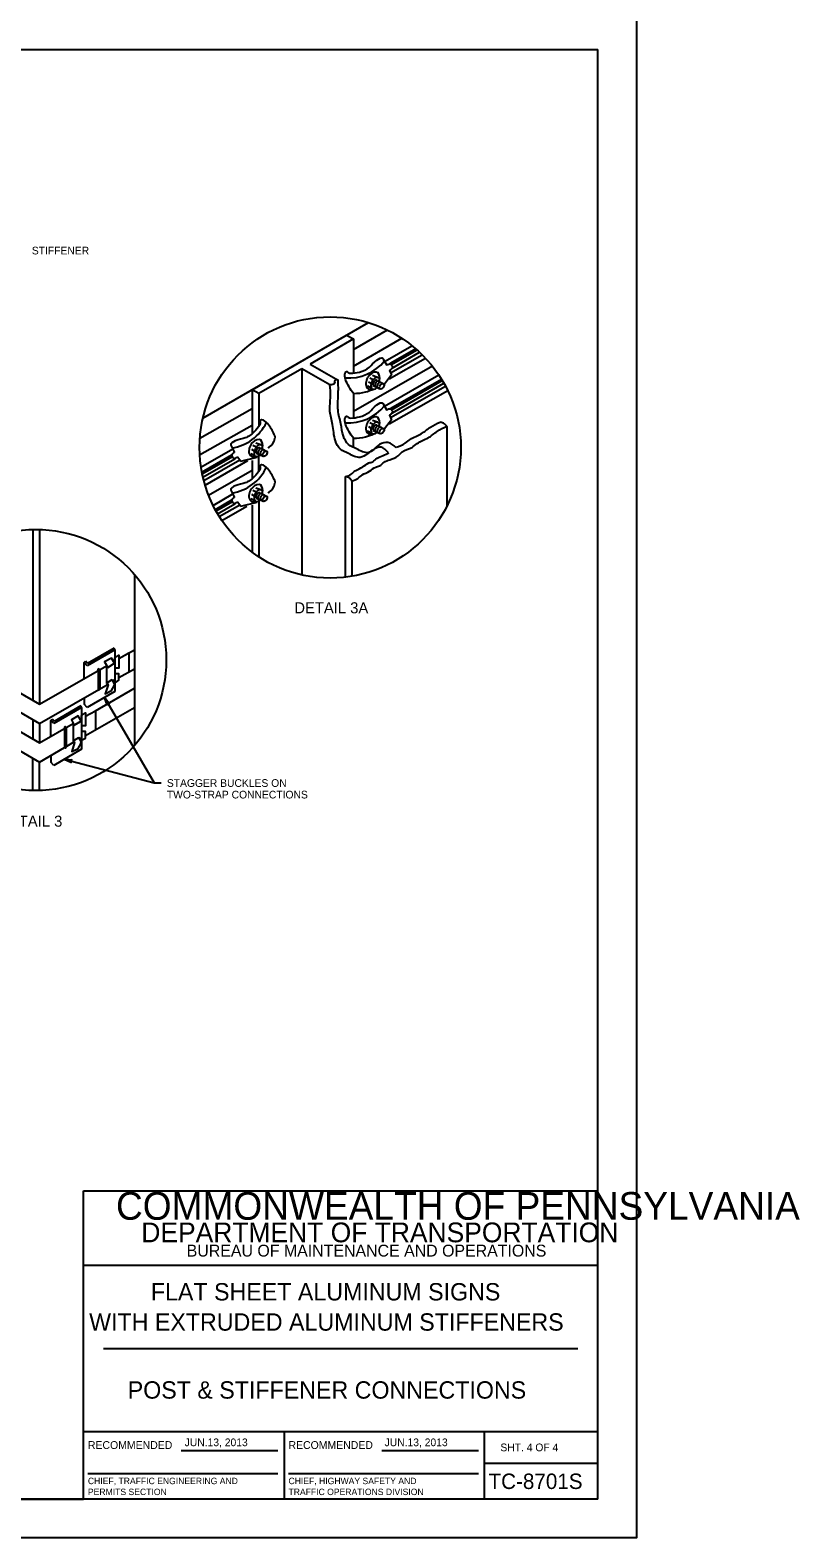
# Model space of a CAD drawing. Extents: x 650495 to 652241, y 298458 to 299646.
# Drawn here: x 651942 to 652241, y 298458 to 299044 of the extents above; entities that cross this region are included whole.
import ezdxf

# ---------------------------------------------------------------- set-up
doc = ezdxf.new("R2010")
doc.units = 0
for name, color, linetype in [('1', 7, 'Continuous'), ('2', 7, 'Continuous'), ('3', 7, 'Continuous'), ('PLT-BNDY', 7, 'Continuous')]:
    doc.layers.add(name, color=color, linetype=linetype)

# ---------------------------------------------------------------- blocks, each defined once
blk = doc.blocks.new('RARROW')
at = {"layer": '3'}
blk.add_lwpolyline([(-2.2695, 0.285), (-2.184875, 0.12075), (0, 0), (-2.2695, 0.285), (-2.38575, 0.384625), (0, 0), (-2.183125, -0.108), (-2.262875, -0.2705), (0, 0), (-2.38575, -0.379125), (-2.262875, -0.2705)], dxfattribs=at)

msp = doc.modelspace()

# ---------------------------------------------------------------- linework, layer by layer
at = {"layer": '1'}
for p, q in [((651376.31, 299036.63), (652162.31, 299036.63)), ((652162.31, 298472.63), (652162.31, 299036.63)), ((651962.31, 298472.63), (651962.31, 298592.63)), ((651962.31, 298592.63), (652162.31, 298592.63)), ((652162.31, 298563.63), (651962.31, 298563.63)), ((651970.06, 298531.31), (652154.56, 298531.31)), ((651962.31, 298499), (652162.31, 298499)), ((652040.31, 298499), (652040.31, 298472.63)), ((652118.19, 298472.63), (652118.19, 298499)), ((652000.24, 298491.57), (652037.87, 298491.57)), ((652078.24, 298491.57), (652115.87, 298491.57)), ((651963.99, 298482.68), (652037.87, 298482.68)), ((652041.99, 298482.68), (652115.87, 298482.68)), ((652118.19, 298486.63), (652162.31, 298486.63)), ((652162.31, 298472.63), (651376.31, 298472.63)), ((651376.31, 298472.63), (651962.31, 298472.63))]:
    msp.add_line(p, q, dxfattribs=at)
at = {"layer": '2'}
for p, q in [((652008.69, 298893.25), (652073.06, 298930.38)), ((652067.31, 298919.88), (652080.44, 298927.5)), ((652080.44, 298927.5), (652080.44, 298927.5)), ((652027.81, 298904.25), (652064.56, 298925.5)), ((652067.31, 298924), (652050.44, 298914.25)), ((652064.56, 298925.5), (652067.31, 298924)), ((652067.31, 298913.38), (652086.06, 298924.25)), ((652067.31, 298924), (652067.31, 298910.79)), ((652078.81, 298916.13), (652080.19, 298913.75)), ((652079.56, 298915.4), (652089.94, 298921.38)), ((652081.19, 298908.45), (652095.31, 298916.5)), ((652091.56, 298920.13), (652081.59, 298914.4)), ((652081.69, 298910.88), (652093.94, 298917.88)), ((652082.04, 298914.01), (652092.06, 298919.75)), ((652082.31, 298912.63), (652092.94, 298918.88)), ((652047.19, 298912.38), (652030.44, 298902.75)), ((652047.19, 298912.38), (652047.19, 298832.13)), ((652058.05, 298906.12), (652047.19, 298912.38)), ((652050.44, 298914.25), (652061.25, 298908.02)), ((652067.31, 298895.95), (652097.94, 298913.5)), ((652074.69, 298909.88), (652076.56, 298909.13)), ((652082.06, 298910), (652079.31, 298906.44)), ((652079.34, 298897.84), (652100.44, 298910)), ((652081.31, 298911.75), (652082.06, 298910)), ((652027.81, 298904.25), (652027.81, 298887.25)), ((652030.44, 298902.75), (652027.81, 298904.25)), ((652072.69, 298905.75), (652074.44, 298904.75)), ((652073.06, 298907.38), (652074.19, 298906.75)), ((652073.69, 298908.88), (652074.94, 298908.25)), ((652074.19, 298907.75), (652074.19, 298907.75)), ((652074.94, 298905.88), (652077.56, 298904.63)), ((652076.44, 298907.88), (652078.81, 298906.63)), ((652081.19, 298891.02), (652103.92, 298903.98)), ((652081.54, 298896.9), (652101.44, 298908.38)), ((652081.69, 298893.45), (652103.07, 298905.67)), ((652082, 298896.43), (652101.81, 298907.88)), ((652082.44, 298895.22), (652102.44, 298906.75)), ((652030.44, 298902.75), (652030.44, 298890.13)), ((652067.31, 298902.65), (652067.31, 298893.24)), ((652078.81, 298898.7), (652080.19, 298896.32)), ((652007.56, 298885.38), (652027.81, 298897)), ((652074.69, 298892.45), (652076.56, 298891.7)), ((652082.06, 298892.57), (652079.31, 298889.01)), ((652081.31, 298894.32), (652082.06, 298892.57)), ((652007.44, 298878.88), (652027.81, 298890.5)), ((652072.69, 298888.32), (652074.44, 298887.32)), ((652073.06, 298889.95), (652074.19, 298889.32)), ((652073.69, 298891.45), (652074.94, 298890.82)), ((652074.19, 298890.32), (652074.19, 298890.32)), ((652074.94, 298888.45), (652077.56, 298887.2)), ((652076.44, 298890.45), (652078.81, 298889.2)), ((652103.56, 298889.99), (652103.56, 298858.75)), ((652007.94, 298874.13), (652020.31, 298881.25)), ((652019.69, 298882.38), (652021.06, 298879.88)), ((652027.56, 298881.13), (652028.69, 298880.5)), ((652028.19, 298882.63), (652029.56, 298882)), ((652028.69, 298881.5), (652028.69, 298881.5)), ((652029.31, 298883.63), (652031.19, 298882.88)), ((652030.94, 298881.63), (652033.44, 298880.38)), ((652067.31, 298881.77), (652067.31, 298885.22)), ((652008.31, 298872.13), (652019.94, 298878.88)), ((652008.44, 298871.5), (652020.44, 298878.38)), ((652008.69, 298870.25), (652021.19, 298877.38)), ((652009.06, 298868.88), (652023.06, 298877)), ((652009.56, 298867.13), (652026.22, 298876.68)), ((652022.31, 298878), (652023.44, 298876.5)), ((652023.44, 298876.5), (652029.76, 298878.05)), ((652027.31, 298879.5), (652028.94, 298878.5)), ((652027.81, 298876.77), (652027.81, 298869.75)), ((652029.56, 298879.63), (652032.19, 298878.38)), ((652030.44, 298872.63), (652030.44, 298878.37)), ((652010.94, 298863.25), (652027.81, 298873)), ((652064.06, 298870.43), (652064.06, 298831.31)), ((652066.69, 298868.81), (652066.69, 298831.68)), ((652012.69, 298859.25), (652020.31, 298863.75)), ((652019.69, 298864.88), (652021.06, 298862.38)), ((652027.56, 298863.63), (652028.69, 298863)), ((652028.19, 298865.13), (652029.56, 298864.5)), ((652028.69, 298864), (652028.69, 298864)), ((652029.31, 298866.13), (652031.19, 298865.38)), ((652030.94, 298864.13), (652033.44, 298862.88)), ((652013.56, 298857.63), (652019.94, 298861.38)), ((652013.81, 298857.13), (652020.44, 298860.88)), ((652014.44, 298856), (652021.19, 298859.88)), ((652015.06, 298854.88), (652023.06, 298859.5)), ((652016.06, 298853.38), (652025.79, 298858.94)), ((652022.31, 298860.5), (652023.44, 298859)), ((652023.44, 298859), (652029.78, 298860.56)), ((652027.31, 298862), (652028.94, 298861)), ((652027.81, 298859.36), (652027.81, 298841.13)), ((652029.56, 298862.13), (652032.19, 298860.88)), ((652030.44, 298860.89), (652030.44, 298839.25)), ((651942.56, 298849.88), (651942.56, 298783.5)), ((651945.19, 298849.88), (651945.19, 298781.88)), ((651982.06, 298832.38), (651982.06, 298765.88)), ((651962.56, 298798.13), (651963.06, 298798.63)), ((651963.81, 298797.75), (651963.06, 298798.63)), ((651974.44, 298803.13), (651963.69, 298796.88)), ((651974.19, 298803.75), (651963.81, 298797.75)), ((651974.44, 298803.13), (651974.19, 298803.75)), ((651974.44, 298803.13), (651974.44, 298786.88)), ((651976.06, 298799.75), (651979.94, 298801.88)), ((651979.94, 298801.88), (651979.94, 298794.38)), ((651982.06, 298803.13), (651982.06, 298795.63)), ((651962.56, 298791.88), (651962.56, 298798.13)), ((651963.69, 298796.88), (651962.56, 298798.13)), ((651967.94, 298795), (651967.94, 298787.5)), ((651968.56, 298795.38), (651968.56, 298787.88)), ((651969.06, 298795.63), (651969.06, 298795.63)), ((651971.19, 298796.88), (651971.19, 298790)), ((651974.44, 298786.88), (651963.69, 298780.63)), ((651971.19, 298790.13), (651973.44, 298791.5)), ((651982.06, 298788.13), (651982.06, 298780.63)), ((651961.19, 298781.25), (651950.81, 298775.25)), ((651961.44, 298780.63), (651961.19, 298781.25)), ((651962.56, 298784.38), (651962.56, 298781.88)), ((651963.69, 298780.63), (651962.56, 298781.88)), ((651970.38, 298784.52), (651989.81, 298751.38)), ((651942.56, 298776), (651942.56, 298768.5)), ((651949.56, 298775.63), (651950.06, 298776.13)), ((651950.69, 298774.38), (651949.56, 298775.63)), ((651949.56, 298769.38), (651949.56, 298775.63)), ((651950.81, 298775.25), (651950.06, 298776.13)), ((651961.44, 298780.63), (651950.69, 298774.38)), ((651961.44, 298780.63), (651961.44, 298764.38)), ((651963.06, 298777.25), (651966.94, 298779.38)), ((651966.94, 298779.38), (651966.94, 298771.88)), ((651969.06, 298780.63), (651969.06, 298780.63)), ((651945.19, 298774.38), (651945.19, 298766.88)), ((651954.94, 298772.5), (651954.94, 298765)), ((651955.56, 298772.88), (651955.56, 298765.38)), ((651958.19, 298774.38), (651958.19, 298767.5)), ((651958.19, 298767.63), (651960.44, 298769)), ((651961.44, 298764.38), (651950.69, 298758.13)), ((651942.56, 298748.25), (651942.56, 298761)), ((651945.19, 298748.38), (651945.19, 298759.38)), ((651949.56, 298761.88), (651949.56, 298759.38)), ((651950.69, 298758.13), (651949.56, 298759.38)), ((651954.69, 298760.5), (651989.81, 298751.38)), ((651989.81, 298751.38), (651992.44, 298751.38)), ((651989.81, 298751.38), (651992.44, 298751.38))]:
    msp.add_line(p, q, dxfattribs=at)
for points in [[(651908.44, 298803.13), (651945.19, 298781.88), (651971.19, 298796.88)], [(651973.94, 298798.5), (651974.44, 298798.75)], [(651974.44, 298798.75), (651974.44, 298800), (651976.06, 298801), (651976.06, 298796), (651974.44, 298796)], [(651976.06, 298799.75), (651982.06, 298803.13)], [(651908.94, 298795.38), (651945.19, 298774.38), (651971.81, 298789.75)], [(651974.44, 298790.38), (651975.56, 298791), (651976.06, 298791.25), (651976.06, 298793.75), (651974.44, 298793.75)], [(651976.06, 298792.25), (651982.06, 298795.63)], [(651908.44, 298788.13), (651945.19, 298766.88), (651958.31, 298774.38)], [(651966.94, 298779.38), (651982.06, 298788.13)], [(651971.19, 298790), (651971.44, 298789.75), (651971.69, 298789.75), (651971.81, 298789.5), (651970.69, 298786), (651973.19, 298787.25), (651974.19, 298789), (651974.31, 298789.88), (651973.44, 298791.5)], [(651971.81, 298789.5), (651970.69, 298786)], [(651973.44, 298791.5), (651974.31, 298789.88), (651974.44, 298791.25), (651973.81, 298790.88), (651974.19, 298790.25), (651974.19, 298791.13), (651973.94, 298790.88), (651974.19, 298790.5)], [(651973.81, 298790.88), (651974.44, 298791.25)], [(651908.94, 298780.38), (651945.19, 298759.38), (651958.69, 298767.25)], [(651960.94, 298776), (651961.31, 298775.38), (651958.69, 298773.75), (651958.19, 298774.38)], [(651960.94, 298776), (651961.44, 298776.25)], [(651961.44, 298776.25), (651961.44, 298777.5), (651963.06, 298778.5), (651963.06, 298773.5), (651961.44, 298773.5)], [(651963.06, 298769.75), (651982.06, 298780.63)], [(651958.19, 298767.5), (651958.44, 298767.25), (651958.69, 298767.25), (651958.81, 298767), (651957.69, 298763.5), (651960.19, 298764.75), (651961.19, 298766.5), (651961.31, 298767.38), (651960.44, 298769)], [(651960.44, 298769), (651961.31, 298767.38), (651961.44, 298768.75), (651960.81, 298768.38), (651961.19, 298767.75), (651961.19, 298768.63), (651960.94, 298768.38), (651961.19, 298768)], [(651961.44, 298767.88), (651962.56, 298768.5), (651963.06, 298768.75), (651963.06, 298771.25), (651961.44, 298771.25)], [(651958.81, 298767), (651957.69, 298763.5)], [(651960.81, 298768.38), (651961.44, 298768.75)]]:
    msp.add_lwpolyline(points, dxfattribs=at)
for points in [[(651974.31, 298797.88), (651973.19, 298799.88), (651970.44, 298798.38), (651971.69, 298796.25)], [(651961.31, 298775.38), (651960.19, 298777.38), (651957.56, 298775.88), (651958.69, 298773.75)]]:
    msp.add_lwpolyline(points, close=True, dxfattribs=at)
for centre in [(652058.22, 298881.78), (651943.66, 298799.11)]:
    msp.add_circle(centre, 50.81, dxfattribs=at)
for centre, radius, start, end in [((652065.4, 298926.68), 17.87, 265.83165, 321.14733), ((652074.11, 298908.77), 3.36, 347.37836, 39.19138), ((652076.37, 298908.06), 1.04, 326.30993, 77.29289), ((652065.4, 298909.25), 17.87, 265.83165, 321.14733), ((652074.11, 298891.35), 3.36, 347.37836, 39.19138), ((652017.3, 298899.25), 17.87, 278.85259, 334.16826), ((652076.37, 298890.63), 1.04, 326.30993, 77.29289), ((652030.9, 298881.81), 1.04, 326.30993, 77.29289), ((652028.64, 298882.52), 3.36, 347.37836, 39.19138), ((652017.3, 298881.75), 17.87, 278.85259, 334.85047), ((652030.9, 298864.31), 1.04, 326.30993, 77.29289), ((652028.64, 298865.02), 3.36, 347.37836, 39.19138), ((651968.2, 298795.29), 0.328, 12.47174, 227.52972), ((651968.21, 298787.77), 0.321, 223.05577, 16.94568), ((651955.21, 298772.79), 0.328, 12.47174, 227.52972), ((651955.22, 298765.27), 0.321, 223.05577, 16.94568)]:
    msp.add_arc(centre, radius, start, end, dxfattribs=at)
for centre, major_axis, ratio, start_param, end_param in [((652074.87, 298907.73), (-1.86, -3.16), 0.66529, 3.112342, 6.959485), ((652075.82, 298906.78), (-1.19, -2.21), 0.589639, 3.346784, 7.343149), ((652075.7, 298906.88), (-0.705, -0.983), 0.589639, 3.251776, 6.551705), ((652076.49, 298906.57), (-0.705, -0.983), 0.589639, 3.009528, 6.308804), ((652077.28, 298906.05), (-0.705, -0.983), 0.589639, 3.009528, 6.308804), ((652074.87, 298890.3), (-1.86, -3.16), 0.66529, 3.112342, 6.959485), ((652075.82, 298889.35), (-1.19, -2.21), 0.589639, 3.346784, 7.343149), ((652075.7, 298889.46), (-0.705, -0.983), 0.589639, 3.251776, 6.551705), ((652076.49, 298889.14), (-0.705, -0.983), 0.589639, 3.009528, 6.308804), ((652077.28, 298888.62), (-0.705, -0.983), 0.589639, 3.009528, 6.308804), ((652029.4, 298881.48), (-1.86, -3.16), 0.66529, 3.112342, 7.061537), ((652030.35, 298880.53), (-1.19, -2.21), 0.589639, 3.346784, 7.304711), ((652030.23, 298880.63), (-0.705, -0.983), 0.589639, 3.251776, 6.551705), ((652031.02, 298880.32), (-0.705, -0.983), 0.589639, 3.009528, 6.308804), ((652031.82, 298879.8), (-0.705, -0.983), 0.589639, 3.009528, 6.308804), ((652029.4, 298863.98), (-1.86, -3.16), 0.66529, 3.112342, 6.979702), ((652030.35, 298863.03), (-1.19, -2.21), 0.589639, 3.346784, 7.348359), ((652030.23, 298863.13), (-0.705, -0.983), 0.589639, 3.251776, 6.551705), ((652031.02, 298862.82), (-0.705, -0.983), 0.589639, 3.009528, 6.308804), ((652031.82, 298862.3), (-0.705, -0.983), 0.589639, 3.009528, 6.308804)]:
    msp.add_ellipse(centre, major_axis=major_axis, ratio=ratio, start_param=start_param, end_param=end_param, dxfattribs=at)
for centre in [(652078.27, 298905.58), (652078.27, 298888.15), (652032.81, 298879.33), (652032.81, 298861.83)]:
    msp.add_ellipse(centre, major_axis=(-0.705, -0.983), ratio=0.589639, dxfattribs=at)
for points in [[(652066.19, 298910.63), (652069.56, 298911.13), (652073.44, 298913), (652076.31, 298915.75), (652078.69, 298916.38), (652078.81, 298916.13)], [(652067.38, 298902.65), (652064.19, 298908.25), (652064.06, 298910.88), (652064.19, 298911.13), (652064.44, 298911.25)], [(652064.44, 298911.25), (652064.56, 298911.38), (652065.19, 298911), (652066.19, 298910.63)], [(652080.19, 298913.75), (652081.69, 298914.25), (652082.31, 298912.63), (652081.31, 298911.63), (652081.31, 298911.5)], [(652080.81, 298879.88), (652078, 298881.86), (652072.71, 298879.34), (652069.87, 298877.91), (652065.37, 298879.41), (652062.22, 298881.15), (652060.24, 298884.39), (652059.13, 298890.78), (652058.11, 298895.79), (652058.34, 298901.69), (652058.11, 298906.11)], [(652061.32, 298908.01), (652059.98, 298907.81), (652059.9, 298906.75), (652059.27, 298906.28), (652058.13, 298906.12)], [(652083.92, 298881.71), (652080.68, 298883.72), (652077.44, 298882.97), (652072.98, 298879.74), (652068.48, 298881.24), (652065.32, 298882.98), (652063.35, 298886.21), (652062.37, 298890.94), (652061.26, 298896.27), (652061.34, 298902.19), (652061.32, 298908.01)], [(652075.14, 298904.38), (652071.94, 298903.25), (652067.31, 298902.64)], [(652066.19, 298893.2), (652069.56, 298893.7), (652073.44, 298895.57), (652076.31, 298898.32), (652078.69, 298898.95), (652078.81, 298898.7)], [(652031.06, 298892.38), (652030.94, 298892.25), (652030.94, 298891.5), (652030.81, 298890.5)], [(652036.44, 298886.88), (652033.81, 298891.13), (652031.69, 298892.5), (652031.44, 298892.5), (652031.06, 298892.38)], [(652067.38, 298885.23), (652064.19, 298890.82), (652064.06, 298893.45), (652064.19, 298893.7), (652064.44, 298893.82)], [(652064.44, 298893.82), (652064.56, 298893.95), (652065.19, 298893.57), (652066.19, 298893.2)], [(652080.19, 298896.32), (652081.69, 298896.82), (652082.31, 298895.2), (652081.31, 298894.2), (652081.31, 298894.07)], [(652030.81, 298890.5), (652028.69, 298887.88), (652025.19, 298885.5), (652021.31, 298884.38), (652019.56, 298882.63), (652019.69, 298882.38)], [(652034.06, 298881.63), (652034.44, 298881.88), (652036.69, 298885.25), (652036.69, 298886.38), (652036.19, 298887.13)], [(652066.69, 298868.81), (652068.96, 298869.75), (652070.62, 298871.09), (652073.54, 298872.59), (652075.91, 298874.17), (652077.4, 298874.64), (652079.06, 298875.98), (652081.43, 298877.01), (652084.59, 298878.59), (652086.16, 298880.09), (652090.03, 298881.82), (652092, 298883.32), (652096.26, 298885.53), (652099.81, 298888.06), (652103.56, 298890.06)], [(652075.14, 298886.95), (652071.94, 298885.82), (652067.31, 298885.22)], [(652083.82, 298881.88), (652087.39, 298883.44), (652089.36, 298884.94), (652093.62, 298887.15), (652097.17, 298889.68), (652100.92, 298891.67)], [(652103.6, 298889.95), (652102.72, 298890.97), (652100.97, 298891.58)], [(652021.06, 298879.88), (652019.94, 298878.88), (652021.06, 298877.5), (652022.31, 298878), (652022.44, 298877.88)], [(652031.06, 298874.88), (652030.94, 298874.75), (652030.94, 298874), (652030.81, 298873)], [(652036.44, 298869.38), (652033.81, 298873.63), (652031.69, 298875), (652031.44, 298875), (652031.06, 298874.88)], [(652064.05, 298870.42), (652066.32, 298871.36), (652067.98, 298872.71), (652070.9, 298874.21), (652073.27, 298875.78), (652074.76, 298876.26), (652076.42, 298877.6), (652078.79, 298878.63), (652081.02, 298879.71)], [(652030.81, 298873), (652028.69, 298870.38), (652025.19, 298868), (652021.31, 298866.88), (652019.56, 298865.13), (652019.69, 298864.88)], [(652034.06, 298864.13), (652034.44, 298864.38), (652036.69, 298867.75), (652036.69, 298868.88), (652036.19, 298869.63)], [(652066.69, 298868.81), (652065.81, 298869.82), (652064.06, 298870.43)], [(652021.06, 298862.38), (652019.94, 298861.38), (652021.06, 298860), (652022.31, 298860.5), (652022.44, 298860.38)]]:
    msp.add_spline(points, degree=3, dxfattribs=at)
at = {"layer": 'PLT-BNDY'}
msp.add_lwpolyline([(651336.31, 299051.63), (652177.31, 299051.63), (652177.31, 298457.63), (651336.31, 298457.63)], close=True, dxfattribs=at)

# ---------------------------------------------------------------- block references
at = {"layer": '2'}
for p, xscale, yscale, rotation in [((651970.38, 298784.52), 1.2574347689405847, 1.3092961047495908, 120.9356690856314), ((651954.69, 298760.5), 1.257434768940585, 1.3092961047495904, 165.6401293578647)]:
    msp.add_blockref('RARROW', p, dxfattribs=dict(at, xscale=xscale, yscale=yscale, rotation=rotation))

# ---------------------------------------------------------------- texts
at = {"layer": '1'}
for s, height, p in [('COMMONWEALTH OF PENNSYLVANIA', 10.7828, (651974.9, 298581.36)), ('DEPARTMENT OF TRANSPORTATION', 7.6837, (651984.76, 298572.61)), ('BUREAU OF MAINTENANCE AND OPERATIONS', 4.6253, (652002.41, 298567.04)), ('FLAT SHEET ALUMINUM SIGNS', 6.75, (651988.47, 298549.97)), ('WITH EXTRUDED ALUMINUM STIFFENERS', 6.75, (651964.47, 298538.22)), ('POST & STIFFENER CONNECTIONS', 6.75, (651979.47, 298511.78)), ('RECOMMENDED', 3.048, (651963.99, 298492.2)), ('RECOMMENDED', 3.048, (652041.99, 298492.2)), ('SHT. 4 OF 4', 3, (652124.4, 298491.31)), ('TC-8701S', 6, (652119.79, 298476.63)), ('CHIEF, TRAFFIC ENGINEERING AND', 2.5, (651963.99, 298478.51)), ('PERMITS SECTION', 2.5, (651963.99, 298474.26)), ('TRAFFIC OPERATIONS DIVISION', 2.5, (652041.99, 298474.26)), ('CHIEF, HIGHWAY SAFETY AND', 2.5, (652041.99, 298478.51))]:
    msp.add_text(s, height=height, dxfattribs=at).set_placement(p)
at = {"layer": '2'}
for s, height, p in [('STIFFENER', 3, (651942.19, 298956.88)), ('DETAIL 3A', 4.3, (652044.26, 298817.27)), ('STAGGER BUCKLES ON', 3, (651994.69, 298749.75)), ('TWO-STRAP CONNECTIONS', 3, (651994.69, 298745.25)), ('DETAIL 3', 4.3, (651929.11, 298734.27)), ('JUN.13, 2013', 3, (652001.61, 298493.28)), ('JUN.13, 2013', 3, (652079.37, 298493.28))]:
    msp.add_text(s, height=height, dxfattribs=at).set_placement(p)

doc.saveas('drawing.dxf')
